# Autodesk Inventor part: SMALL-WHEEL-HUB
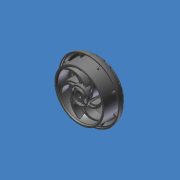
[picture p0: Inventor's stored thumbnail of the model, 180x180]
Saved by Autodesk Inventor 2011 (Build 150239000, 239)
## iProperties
Created: 2007-08
Part Number: SMALL-WHEEL-HUB
Material: ABS Plastic
Document SubType Name: Modeling
Density: 1.06 g/cm^3
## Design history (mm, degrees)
feature "Base1"
body "Solid1"
